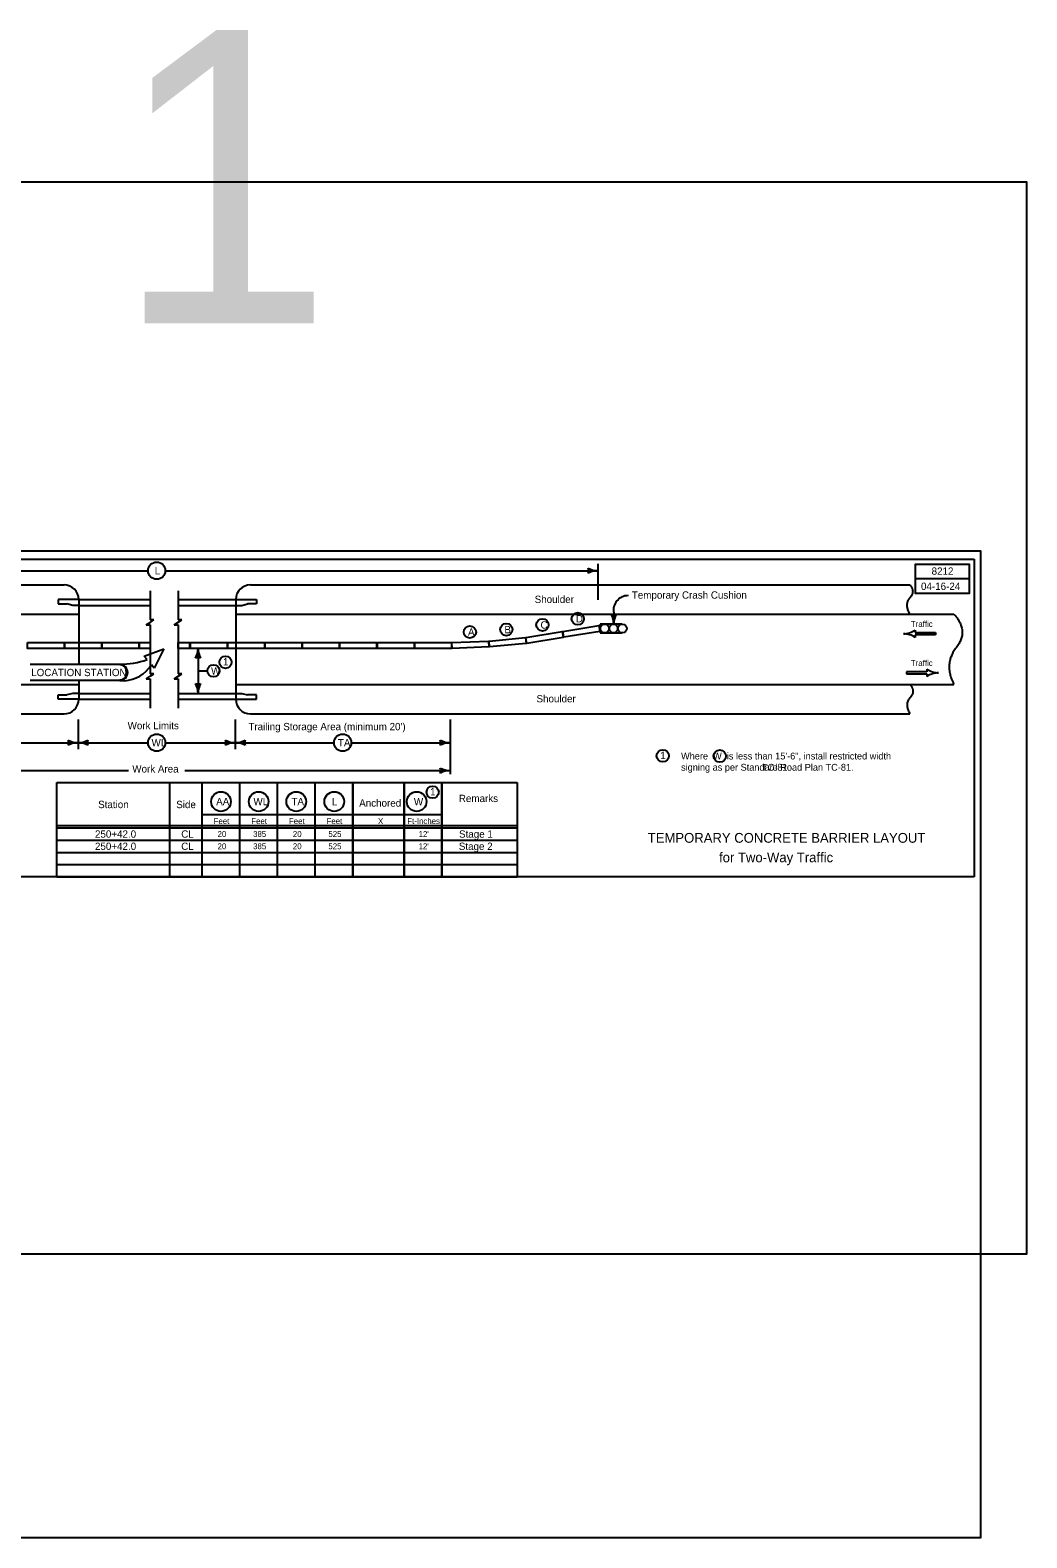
# Model space of a CAD drawing. Extents: x 10041 to 81668, y 7924 to 11018.
# Drawn here: x 11324 to 13362, y 7924 to 11009 of the extents above; entities that cross this region are included whole.
import ezdxf

# ---------------------------------------------------------------- set-up
doc = ezdxf.new("R2010")
doc.units = 0
for name, color, linetype in [('dsnCellElements', 7, 'Continuous'), ('dsnStdNameDate', 7, 'Continuous'), ('Level 1', 7, 'Continuous'), ('Level 10', 7, 'Continuous'), ('Level 12', 7, 'Continuous'), ('Level 5', 7, 'Continuous'), ('Level 6', 7, 'Continuous'), ('Level 60', 7, 'Continuous'), ('Level 63', 7, 'Continuous'), ('SheetAddendum', 7, 'Continuous'), ('SheetBorder', 7, 'Continuous'), ('SheetText', 7, 'Continuous')]:
    doc.layers.add(name, color=color, linetype=linetype)

msp = doc.modelspace()

# ---------------------------------------------------------------- linework, layer by layer
at = {"layer": 'dsnCellElements'}
msp.add_lwpolyline([(10041.2, 8505), (13362.1, 8505), (13362.1, 10698.4), (10041.2, 10698.4)], close=True, dxfattribs=at)
at = {"layer": 'Level 1'}
for p, q in [((12484.7, 9916.9), (12484.7, 9843.3)), ((10264.4, 9874.1), (11392.9, 9874.1)), ((10632, 9903.1), (11564.9, 9903.1)), ((11599.9, 9903.1), (12484.7, 9903.1)), ((11612.6, 9903.1), (11743.1, 9903.1)), ((11774.3, 9874.1), (13122.7, 9874.1)), ((11422.9, 9844.1), (11380.9, 9844.1)), ((11380.9, 9844.1), (11380.9, 9835.1)), ((11422.9, 9844.1), (11568.9, 9844.1)), ((11422.9, 9844.1), (11422.9, 9711)), ((11568.9, 9862.1), (11568.9, 9802.2)), ((11626, 9862.1), (11626, 9802.2)), ((11626, 9844.1), (11744.3, 9844.1)), ((11744.3, 9844.1), (11786.3, 9844.1)), ((11744.3, 9844.1), (11744.3, 9640.1)), ((11786.3, 9844.1), (11786.3, 9835.1)), ((10180.8, 9814.1), (11422.9, 9814.1)), ((11380.9, 9835.1), (11398.9, 9835.1)), ((11410.9, 9832.1), (11398.9, 9835.1)), ((11422.9, 9832.1), (11410.9, 9832.1)), ((11422.9, 9832.1), (11568.9, 9832.1)), ((11626, 9832.1), (11744.3, 9832.1)), ((11744.3, 9832.1), (11756.3, 9832.1)), ((11744.3, 9814.1), (13213.1, 9814.1)), ((11756.3, 9832.1), (11768.3, 9835.1)), ((11786.3, 9835.1), (11768.3, 9835.1)), ((12517.2, 9816.7), (12517.2, 9794.2)), ((11560.9, 9792.1), (11568.9, 9797.1)), ((11560.9, 9792.1), (11568.9, 9792.1)), ((11568.9, 9797.1), (11576.9, 9802.2)), ((11576.9, 9802.2), (11568.9, 9802.2)), ((11568.9, 9792.1), (11568.9, 9742.1)), ((11618, 9792.1), (11634, 9802.2)), ((11618, 9792.1), (11626, 9792.1)), ((11634, 9802.2), (11626, 9802.2)), ((11626, 9792.1), (11626, 9742.1)), ((12534.7, 9793.9), (12489.7, 9793.9)), ((12489.7, 9793.9), (12489.7, 9775.9)), ((12491, 9781.6), (12489.7, 9781.3)), ((13133.8, 9781.5), (13133.8, 9776.3)), ((12489.2, 9777.9), (12489.2, 9777.9)), ((12489.7, 9775.9), (12534.7, 9775.9)), ((13109.9, 9774), (13109.9, 9774)), ((13133.8, 9776.3), (13175.1, 9776.3)), ((13175.1, 9771.8), (13133.8, 9771.8)), ((13133.8, 9771.8), (13133.8, 9766.5)), ((13175.1, 9776.3), (13175.1, 9771.8)), ((11568.9, 9742.1), (11568.9, 9692.2)), ((11626, 9742.1), (11626, 9692.2)), ((11667, 9744.1), (11667, 9652.1)), ((11568.9, 9687.1), (11576.9, 9692.2)), ((11576.9, 9692.2), (11568.9, 9692.2)), ((11618, 9682.1), (11634, 9692.2)), ((11634, 9692.2), (11626, 9692.2)), ((11667, 9698.1), (11686.2, 9698.1)), ((13157.4, 9696.4), (13116.2, 9696.4)), ((13116.2, 9696.4), (13116.2, 9691.9)), ((13116.2, 9691.9), (13157.4, 9691.9)), ((13157.4, 9701.6), (13157.4, 9696.4)), ((13157.4, 9691.9), (13157.4, 9686.6)), ((13181.3, 9694.1), (13181.3, 9694.1)), ((10180.8, 9670.1), (11422.9, 9670.1)), ((11422.9, 9678.5), (11422.9, 9640.1)), ((11560.9, 9682.1), (11568.9, 9687.1)), ((11560.9, 9682.1), (11568.9, 9682.1)), ((11568.9, 9682.1), (11568.9, 9622.1)), ((11618, 9682.1), (11626, 9682.1)), ((11626, 9682.1), (11626, 9622.1)), ((11744.3, 9670.1), (13213.1, 9670.1)), ((11380.9, 9649.1), (11398.9, 9649.1)), ((11380.9, 9640.1), (11380.9, 9649.1)), ((11422.9, 9640.1), (11380.9, 9640.1)), ((11410.9, 9652.1), (11398.9, 9649.1)), ((11422.9, 9652.1), (11410.9, 9652.1)), ((11422.9, 9652.1), (11568.9, 9652.1)), ((11422.9, 9640.1), (11568.9, 9640.1)), ((11626, 9652.1), (11744.3, 9652.1)), ((11626, 9640.1), (11744.3, 9640.1)), ((11744.3, 9652.1), (11756.3, 9652.1)), ((11744.3, 9640.1), (11786.3, 9640.1)), ((11756.3, 9652.1), (11768.3, 9649.1)), ((11786.3, 9649.1), (11768.3, 9649.1)), ((11786.3, 9640.1), (11786.3, 9649.1)), ((10264.4, 9610.1), (11392.9, 9610.1)), ((11421.7, 9598.9), (11421.7, 9537.6)), ((11743.1, 9598.9), (11743.1, 9537.6)), ((11774.3, 9610.1), (13122.7, 9610.1)), ((12182.6, 9598.9), (12182.6, 9486.5)), ((11195.6, 9551.1), (11421.7, 9551.1)), ((11421.7, 9551.1), (11564.9, 9551.1)), ((11599.9, 9551.1), (11743.1, 9551.1)), ((11612.6, 9551.1), (11743.1, 9551.1)), ((11743.1, 9551.1), (11945.2, 9551.1)), ((11980.5, 9551.1), (12182.6, 9551.1)), ((10934.2, 9494), (11525, 9494)), ((11640.3, 9494), (12182.6, 9494)), ((11641.6, 9494), (11743.1, 9494)), ((11609.4, 9276.7), (11609.4, 9469.7)), ((11675.4, 9276.7), (11675.4, 9469.7)), ((11752.4, 9276.7), (11752.4, 9469.7)), ((11829.4, 9276.7), (11829.4, 9469.7)), ((11906.4, 9276.7), (11906.4, 9469.7)), ((11983.4, 9469.7), (11983.4, 9276.7)), ((12088.9, 9469.7), (12088.9, 9276.7)), ((12165.9, 9469.7), (12165.9, 9276.7)), ((11378.4, 9381.7), (12319.9, 9381.7)), ((11675.4, 9403.9), (12165.9, 9403.9)), ((11378.4, 9376.7), (12319.9, 9376.7))]:
    msp.add_line(p, q, dxfattribs=at)
for points in [[(12413, 9778.7), (12487, 9790.8), (12489, 9778.9), (12414.9, 9766.8)], [(11317.9, 9756.1), (11392.9, 9756.1), (11392.9, 9744.1), (11317.9, 9744.1)], [(11394.4, 9756.1), (11469.4, 9756.1), (11469.4, 9744.1), (11394.4, 9744.1)], [(11470.9, 9756.1), (11545.9, 9756.1), (11545.9, 9744.1), (11470.9, 9744.1)], [(11651.3, 9756.1), (11726.3, 9756.1), (11726.3, 9744.1), (11651.3, 9744.1)], [(11727.8, 9756.1), (11802.8, 9756.1), (11802.8, 9744.1), (11727.8, 9744.1)], [(11804.3, 9756.1), (11879.3, 9756.1), (11879.3, 9744.1), (11804.3, 9744.1)], [(11880.8, 9756.1), (11955.8, 9756.1), (11955.8, 9744.1), (11880.8, 9744.1)], [(11957.3, 9756.1), (12032.3, 9756.1), (12032.3, 9744.1), (11957.3, 9744.1)], [(12033.8, 9756.1), (12108.8, 9756.1), (12108.8, 9744.1), (12033.8, 9744.1)], [(12110.3, 9756.1), (12185.3, 9756.1), (12185.3, 9744.1), (12110.3, 9744.1)], [(12186.3, 9756.1), (12261.3, 9759.1), (12261.7, 9747.1), (12186.8, 9744.1)], [(12262.1, 9759.1), (12336.8, 9766.2), (12337.9, 9754.2), (12263.2, 9747.1)], [(12337.5, 9766.3), (12411.5, 9778.4), (12413.5, 9766.6), (12339.5, 9754.4)]]:
    msp.add_lwpolyline(points, close=True, dxfattribs=at)
for points in [[(11568.9, 9744.1), (11547.4, 9744.1), (11547.4, 9756.1), (11568.9, 9756.1)], [(11568.9, 9756.1), (11568.9, 9744.1)], [(11626, 9744.1), (11626, 9756.1)], [(11626, 9756.1), (11649.8, 9756.1), (11649.8, 9744.1), (11626, 9744.1)]]:
    msp.add_lwpolyline(points, dxfattribs=at)
for centre, radius in [((11582.4, 9903.1), 17.6), ((12443.6, 9804.8), 12.5), ((12223, 9777.6), 12.5), ((12297.5, 9782.5), 12.5), ((12371.3, 9792.1), 12.5), ((12498.7, 9784.9), 9), ((12498.7, 9784.9), 9), ((12516.7, 9784.9), 9), ((12516.7, 9784.9), 9), ((12534.7, 9784.9), 9), ((12534.7, 9784.9), 9), ((11723.2, 9715.7), 12.5), ((11698.7, 9698.1), 12.5), ((11582.4, 9551.1), 17.6), ((11962.8, 9551.1), 17.6), ((12617.4, 9524.2), 12.5), ((12734, 9523.8), 12.5), ((11713.9, 9430.7), 20.1), ((11790.9, 9430.7), 20.1), ((11867.9, 9430.7), 20.1), ((11945.6, 9430.7), 20.1), ((12114.2, 9430.7), 20.1), ((12146.8, 9449.9), 12.5)]:
    msp.add_circle(centre, radius, dxfattribs=at)
for centre, radius, start, end in [((12449.1, 9903.1), 16.4, 342.2666, 17.7333), ((12484.7, 9945.6), 42.5, 241.9275, 270), ((11392.9, 9844.1), 30, 0, 90), ((11774.3, 9844.1), 30, 90, 180), ((12484.7, 9860.6), 42.5, 90, 118.0725), ((12546.7, 9822.1), 30, 90, 190.3537), ((12517.2, 9829.9), 16.4, 252.2666, 287.7334), ((12474.7, 9794.2), 42.5, 0, 28.0725), ((12559.7, 9794.2), 42.5, 151.9275, 180), ((13107.9, 9822.3), 48.4, 272.352, 302.382), ((13107.9, 9725.7), 48.4, 57.618, 87.648), ((11624.5, 9744.1), 42.5, 331.9275, 360), ((11667, 9708.5), 16.4, 72.2666, 107.7334), ((11709.5, 9744.1), 42.5, 180, 208.0725), ((13183.3, 9742.5), 48.4, 237.618, 267.648), ((13183.3, 9645.8), 48.4, 92.352, 122.382), ((11667, 9687.8), 16.4, 252.2666, 287.7333), ((11624.5, 9652.1), 42.5, 360, 28.0725), ((11709.5, 9652.1), 42.5, 151.9275, 180), ((11392.9, 9640.1), 30, 270, 360), ((11774.3, 9640.1), 30, 180, 270), ((11386.1, 9551.1), 16.4, 342.2666, 17.7333), ((11421.7, 9593.6), 42.5, 241.9275, 270), ((11421.7, 9508.6), 42.5, 90, 118.0725), ((11421.7, 9593.6), 42.5, 270, 298.0725), ((11421.7, 9508.6), 42.5, 61.9275, 90), ((11457.3, 9551.1), 16.4, 162.2666, 197.7334), ((11707.4, 9551.1), 16.4, 342.2666, 17.7333), ((11743.1, 9593.6), 42.5, 241.9275, 270), ((11743.1, 9508.6), 42.5, 90, 118.0725), ((11743.1, 9593.6), 42.5, 270, 298.0725), ((11743.1, 9508.6), 42.5, 61.9275, 90), ((11778.7, 9551.1), 16.4, 162.2666, 197.7334), ((12146.9, 9551.1), 16.4, 342.2666, 17.7333), ((12182.6, 9593.6), 42.5, 241.9275, 270), ((12182.6, 9508.6), 42.5, 90, 118.0725), ((12146.9, 9494), 16.4, 342.2666, 17.7333), ((12182.6, 9536.5), 42.5, 241.9275, 270), ((12182.6, 9451.5), 42.5, 90, 118.0725)]:
    msp.add_arc(centre, radius, start, end, dxfattribs=at)
for points in [[(13122.7, 9874.1), (13134.5, 9860), (13110.9, 9835), (13122.2, 9814.2)], [(13213.1, 9814.1), (13244.5, 9779.7), (13191.1, 9711.7), (13213.1, 9670.1)], [(13123.2, 9670.1), (13135, 9656), (13111.4, 9631), (13122.7, 9610.1)]]:
    msp.add_open_spline(points, degree=2, dxfattribs=at)
at = {"layer": 'Level 10'}
for p, q in [((10149.1, 9926.7), (13254.1, 9926.7)), ((13254.1, 9926.7), (13254.1, 9276.7)), ((11557, 9728.5), (11597.2, 9743.5)), ((11562.9, 9721.2), (11557, 9728.5)), ((11597.2, 9743.5), (11577.1, 9703.5)), ((11506.8, 9711), (11323.6, 9711)), ((11506.8, 9710.1), (11506.8, 9711.9)), ((11577.1, 9703.5), (11571.5, 9710.5)), ((11506.8, 9678.5), (11323.6, 9678.5)), ((11506.8, 9677.6), (11506.8, 9679.4)), ((11516.3, 9678), (11506.8, 9677.6))]:
    msp.add_line(p, q, dxfattribs=at)
for centre, major_axis, start_param, end_param in [((11509.6, 9868), (156.9, 0), 4.694293, 5.059134), ((11506.8, 9694.8), (16.3, 0), 4.712389, 7.853982), ((11506.8, 9694.8), (-15.4, 0), 1.570796, 4.712389), ((11511.7, 9748.2), (70.8, 0), 4.776871, 5.71778)]:
    msp.add_ellipse(centre, major_axis=major_axis, ratio=0.995025, start_param=start_param, end_param=end_param, dxfattribs=at)
at = {"layer": 'Level 12'}
for p, q in [((11378.4, 9276.7), (11378.4, 9469.7)), ((11378.4, 9469.7), (12319.9, 9469.7)), ((12319.9, 9469.7), (12319.9, 9276.7))]:
    msp.add_line(p, q, dxfattribs=at)
at = {"layer": 'Level 5'}
msp.add_line((13254.1, 9276.7), (10149.1, 9276.7), dxfattribs=at)
at = {"layer": 'Level 60'}
msp.add_lwpolyline([(13244.1, 9916.7), (13244.1, 9856.7), (13134.1, 9856.7), (13134.1, 9916.7), (13244.1, 9916.7), (13244.1, 9886.7), (13134.1, 9886.7)], dxfattribs=at)
at = {"layer": 'Level 63'}
for p, q in [((11983.4, 9276.7), (11983.4, 9469.7)), ((12088.9, 9276.7), (12088.9, 9469.7)), ((12165.9, 9276.7), (12165.9, 9469.7))]:
    msp.add_line(p, q, dxfattribs=at)
at = {"layer": 'SheetAddendum'}
for p, q in [((11378.4, 9351.7), (12319.9, 9351.7)), ((11378.4, 9326.7), (12319.9, 9326.7)), ((11378.4, 9301.7), (12319.9, 9301.7)), ((11378.4, 9276.4), (12319.9, 9276.4))]:
    msp.add_line(p, q, dxfattribs=at)
at = {"layer": 'SheetBorder'}
msp.add_lwpolyline([(10132.5, 9944), (13267.5, 9944), (13267.5, 7924), (10132.5, 7924)], close=True, dxfattribs=at)

# ---------------------------------------------------------------- texts
at = {"layer": 'dsnStdNameDate'}
for s, p in [('8212', (13167.3, 9894.7)), ('04-16-24', (13145.6, 9863.7))]:
    msp.add_text(s, height=15, dxfattribs=at).set_placement(p)
at = {"layer": 'Level 10'}
msp.add_text('LOCATION STATION', height=15, dxfattribs=at).set_placement((11325.8, 9687.3))
at = {"layer": 'Level 12'}
for s, height, p in [('L', 15, (11578.5, 9895.6)), ('Shoulder', 15, (12355.5, 9837)), ('Temporary Crash Cushion', 15, (12554.2, 9845.8)), ('D', 15, (12439.7, 9797.3)), ('A', 15, (12219.1, 9770.1)), ('B', 15, (12293.6, 9775)), ('C', 15, (12367.4, 9784.6)), ('Traffic', 12, (13124.9, 9788)), ('1', 15, (11717.9, 9709.1)), ('Traffic', 12, (13124.9, 9708.1)), ('W', 15, (11693.6, 9690.6)), ('Shoulder', 15, (12359.2, 9633.6)), ('Work Limits', 15, (11523, 9578.6)), ("Trailing Storage Area (minimum 20')", 15, (11770, 9576.6)), ('WL', 15, (11571.9, 9543.6)), ('TA', 15, (11953, 9543.6)), ('Work Area', 15, (11532.5, 9490.1)), ('1', 15, (12612.2, 9517.6)), ('Where  W  is less than 15\'-6", install restricted width', 14, (12654.9, 9516.8)), ('signing as per Standard Road Plan TC-81.', 14, (12654.9, 9493.8)), ('                                TC-81', 14, (12654.2, 9493.8)), ('1', 15, (12141.6, 9443.3)), ('Remarks', 15, (12200.4, 9429.6)), ('Station', 15, (11462.7, 9417.2)), ('Side', 15, (11622.4, 9417.2)), ('AA', 15, (11704.1, 9423.2)), ('WL', 15, (11780.3, 9423.2)), ('TA', 15, (11858, 9423.2)), ('L', 15, (11940.7, 9422.8)), ('Anchored', 15, (11996.6, 9420.2)), ('W', 15, (12108.5, 9422.8)), ('Feet', 12, (11698.9, 9384.7)), ('Feet', 12, (11775.9, 9384.7)), ('Feet', 12, (11852.9, 9384.7)), ('Feet', 12, (11929.9, 9384.7)), ('X', 12, (12035, 9384.7)), ('Ft-Inches', 12, (12094.9, 9384.7)), ('250+42.0', 15, (11456.2, 9356.7)), ('CL', 15, (11632.6, 9356.7)), ('20', 12, (11706.9, 9358.2)), ('385', 12, (11779.6, 9358.2)), ('20', 12, (11860.9, 9358.2)), ('525', 12, (11933.6, 9358.2)), ("12'", 12, (12118.1, 9358.2)), ('Stage 1', 15, (12200.8, 9356.7)), ('250+42.0', 15, (11456.2, 9331.7)), ('CL', 15, (11632.6, 9331.7)), ('20', 12, (11706.9, 9333.2)), ('385', 12, (11779.6, 9333.2)), ('20', 12, (11860.9, 9333.2)), ('525', 12, (11933.6, 9333.2)), ("12'", 12, (12118.1, 9333.2)), ('Stage 2', 15, (12200.3, 9331.7))]:
    msp.add_text(s, height=height, dxfattribs=at).set_placement(p)
at = {"layer": 'Level 6'}
for s, p in [('TEMPORARY CONCRETE BARRIER LAYOUT', (12586.8, 9346.4)), ('for Two-Way Traffic', (12732.6, 9306.4))]:
    msp.add_text(s, height=20, dxfattribs=at).set_placement(p)
at = {"layer": 'SheetText'}
msp.add_text('1', height=600, dxfattribs=at).set_placement((11496.6, 10409.2))

doc.saveas('drawing.dxf')
